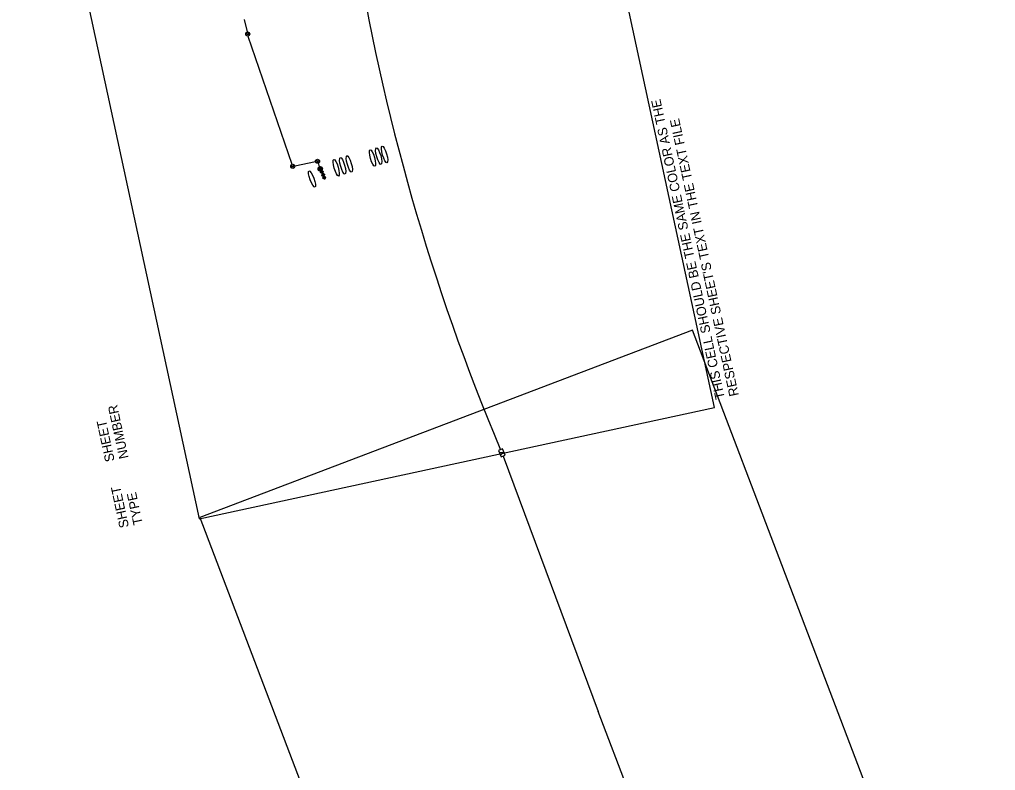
# Model space of a CAD drawing. Extents: x 601462 to 605493, y 331960 to 402715.
# Drawn here: x 601542 to 603347, y 353498 to 354887 of the extents above; entities that cross this region are included whole.
import ezdxf

# ---------------------------------------------------------------- set-up
doc = ezdxf.new("R2010")
doc.units = 0
for name, color, linetype in [('P_FTMS', 7, 'Continuous'), ('P_FTMSConduit', 7, 'Continuous'), ('P_MISC_TXT_2A (Construction)', 7, 'Continuous'), ('P_MISC_TXT_2B (Construction)', 7, 'Continuous')]:
    doc.layers.add(name, color=color, linetype=linetype)

# ---------------------------------------------------------------- blocks, each defined once
blk = doc.blocks.new('FMD')
at = {"layer": 'P_FTMS'}
for p, q in [((17, 18), (-17, 18)), ((-16, 16), (-16, 18)), ((16, 16), (-16, 16)), ((-15, 15), (-15, 20)), ((15, 19), (-15, 19)), ((15, 15), (-15, 15)), ((14, 20), (-14, 20)), ((13, 22), (-13, 22)), ((-13, 13), (-13, 21)), ((13, 13), (-13, 13)), ((-12, 12), (-12, 23)), ((12, 12), (-12, 12)), ((11, 23), (-11, 23)), ((10, 25), (-10, 25)), ((-10, 10), (-10, 24)), ((10, 10), (-10, 10)), ((-9, 9), (-9, 26)), ((9, 9), (-9, 9)), ((8, 26), (-8, 26)), ((7, 28), (-7, 28)), ((-7, 7), (-7, 27)), ((7, 7), (-7, 7)), ((-6, 6), (-6, 29)), ((6, 6), (-6, 6)), ((5, 29), (-5, 29)), ((4, 31), (-4, 31)), ((-4, 4), (-4, 30)), ((4, 4), (-4, 4)), ((-3, 3), (-3, 32)), ((3, 3), (-3, 3)), ((2, 32), (-2, 32)), ((1, 34), (-1, 34)), ((-1, 1), (-1, 33)), ((1, 1), (-1, 1)), ((0, 0), (0, 34)), ((1, 1), (1, 33)), ((3, 3), (3, 32)), ((4, 4), (4, 30)), ((6, 6), (6, 29)), ((7, 7), (7, 27)), ((9, 9), (9, 26)), ((10, 10), (10, 24)), ((12, 12), (12, 23)), ((13, 13), (13, 21)), ((15, 15), (15, 20)), ((16, 16), (16, 18))]:
    blk.add_line(p, q, dxfattribs=at)
blk.add_lwpolyline([(-17, 17), (0, 34), (17, 17), (0, 0)], close=True, dxfattribs=at)
blk = doc.blocks.new('_U233')
at = {"layer": 'P_FTMS'}
for p, q in [((12.1, 1.6), (-12.2, -0.1)), ((11.8, 3), (-12.1, 1.4)), ((11.9, 2.3), (-12.1, 0.6)), ((12.1, 0.8), (-12.1, -0.8)), ((12.1, 0.1), (-12.1, -1.6)), ((11.6, 3.7), (-12, 2.1)), ((-11.9, 2.5), (-11.4, -4.2)), ((11.3, 4.4), (-11.8, 2.9)), ((11, 5.2), (-11.6, 3.6)), ((10.6, 5.9), (-11.4, 4.4)), ((-11.3, 4.5), (-10.6, -6)), ((10.2, 6.6), (-11, 5.1)), ((9.8, 7.3), (-10.7, 5.9)), ((-10.7, 5.9), (-9.8, -7.2)), ((9.2, 8), (-10.2, 6.6)), ((-10, 6.9), (-9, -8.2)), ((8.6, 8.6), (-9.7, 7.4)), ((-9.3, 7.8), (-8.2, -9)), ((7.8, 9.3), (-9, 8.2)), ((-8.6, 8.5), (-7.4, -9.6)), ((6.9, 10), (-8.2, 9)), ((-8, 9.2), (-6.6, -10.2)), ((-7.3, 9.7), (-5.9, -10.6)), ((5.8, 10.7), (-7.2, 9.8)), ((-6.6, 10.3), (-5.1, -11)), ((4.5, 11.3), (-6, 10.6)), ((-5.9, 10.7), (-4.4, -11.4)), ((-5.1, 11), (-3.6, -11.6)), ((-4.4, 11.3), (-2.9, -11.8)), ((2.5, 11.9), (-4.1, 11.5)), ((-3.7, 11.6), (-2.1, -12)), ((-3, 11.8), (-1.4, -12.1)), ((-2.3, 12), (-0.6, -12.2)), ((-1.6, 12.1), (0.1, -12.2)), ((-0.8, 12.1), (0.8, -12.1)), ((-0.1, 12.2), (1.6, -12.1)), ((0.6, 12.1), (2.3, -11.9)), ((1.4, 12.1), (3, -11.8)), ((2.1, 12), (3.7, -11.6)), ((2.9, 11.8), (4.4, -11.3)), ((3.6, 11.6), (5.1, -11)), ((4.4, 11.3), (5.9, -10.7)), ((5.1, 11), (6.6, -10.2)), ((5.9, 10.6), (7.3, -9.8)), ((6.6, 10.2), (8, -9.2)), ((7.4, 9.7), (8.6, -8.6)), ((8.2, 9), (9.3, -7.8)), ((9, 8.2), (10, -6.9)), ((9.8, 7.2), (10.7, -5.8)), ((10.6, 5.9), (11.3, -4.5)), ((11.5, 4), (11.9, -2.5)), ((12.1, -0.6), (-12, -2.3)), ((12.1, -1.4), (-11.8, -3)), ((12, -2.1), (-11.6, -3.7)), ((11.8, -2.9), (-11.3, -4.4)), ((11.6, -3.6), (-11, -5.1)), ((11.3, -4.4), (-10.7, -5.9)), ((11.1, -5.1), (-10.2, -6.6)), ((10.6, -5.9), (-9.8, -7.3)), ((10.2, -6.6), (-9.2, -8)), ((9.6, -7.4), (-8.5, -8.6)), ((9, -8.2), (-7.8, -9.3)), ((8.2, -9), (-6.9, -10)), ((7.3, -9.8), (-5.8, -10.7)), ((6, -10.6), (-4.5, -11.3)), ((4.1, -11.5), (-2.6, -11.9))]:
    blk.add_line(p, q, dxfattribs=at)
blk.add_circle((0, 0), 12.2, dxfattribs=at)
blk = doc.blocks.new('FTMS_FCV')
at = {"layer": 'P_FTMS'}
blk.add_line((13, 16), (1, -22), dxfattribs=at)
blk.add_lwpolyline([(39, 24), (-39, 24), (-39, -24), (39, -24)], close=True, dxfattribs=at)
blk.add_lwpolyline([(-12, 16), (1, -22)], dxfattribs=at)

msp = doc.modelspace()

# ---------------------------------------------------------------- linework, layer by layer
at = {"layer": 'P_FTMS'}
for centre in [(601964.4, 354859.7), (602047.7, 354615.2), (602093.5, 354624.6)]:
    msp.add_circle(centre, 3.75, dxfattribs=at)
for centre, start, end in [((601963.8, 354864.1), 224.5444, 330.8), ((601965, 354855.2), 44.5444, 150.8), ((602047.1, 354619.7), 224.5444, 330.8), ((602048.3, 354610.8), 44.5444, 150.8), ((602092.9, 354629.1), 224.5444, 330.8), ((602094.1, 354620.1), 44.5444, 150.8)]:
    msp.add_arc(centre, 3.75, start, end, dxfattribs=at)
for centre, major_axis in [((602206.7, 354634), (-4.4, 15.4)), ((602217.6, 354637.1), (-4.4, 15.4)), ((602140, 354616.1), (-4.4, 15.4)), ((602152.3, 354619.7), (-4.4, 15.4)), ((602195.2, 354630.6), (-4.4, 15.4)), ((602128.1, 354612.7), (-4.4, 15.4)), ((602083.3, 354591.8), (-5.7, 14.9))]:
    msp.add_ellipse(centre, major_axis=major_axis, ratio=0.23471, dxfattribs=at)
at = {"layer": 'P_FTMSConduit'}
for p, q in [((602046.6, 354618.8), (601965, 354855.2)), ((602051.3, 354616.4), (602089.8, 354623.9)), ((602097.2, 354614.4), (602095.5, 354621.4)), ((602436.7, 354079.4), (602612.7, 353607.2)), ((602781.7, 353163.1), (602612.7, 353607.2))]:
    msp.add_line(p, q, dxfattribs=at)
msp.add_lwpolyline([(601963.8, 354864.1), (601958.2, 354886.6)], dxfattribs=at)
msp.add_arc((606226.2, 355687.6), 4116.5, 189.0802, 202.817, dxfattribs=at)
at = {"layer": 'P_MISC_TXT_2A (Construction)'}
msp.add_lwpolyline([(603347.3, 352840.3), (602787.2, 354312.4), (601876, 353965.7), (602436.1, 352493.6)], close=True, dxfattribs=at)
at = {"layer": 'P_MISC_TXT_2B (Construction)'}
msp.add_lwpolyline([(602827.7, 354169), (602495.5, 355708.6), (601542.4, 355503), (601874.6, 353963.4)], close=True, dxfattribs=at)

# ---------------------------------------------------------------- block references
at = {"layer": 'P_FTMS'}
for name, p, xscale, yscale, rotation in [('_U233', (602098.6, 354610.6), 0.3280833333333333, 0.3280833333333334, -153.80622439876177), ('FMD', (602104.2, 354605.6), 0.16404166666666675, 0.16404166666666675, 112.08663983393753), ('FMD', (602106.4, 354600.4), 0.16404166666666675, 0.16404166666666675, 112.08663983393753), ('FMD', (602108.4, 354595.3), 0.16404166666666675, 0.16404166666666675, 112.08663983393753), ('FTMS_FCV', (602434.3, 354085.4), 0.16404166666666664, 0.1640416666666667, 112.41478162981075)]:
    msp.add_blockref(name, p, dxfattribs=dict(at, xscale=xscale, yscale=yscale, rotation=rotation))

# ---------------------------------------------------------------- texts
at = {"layer": 'P_MISC_TXT_2B (Construction)'}
for s, p in [('THIS CELL SHOULD BE THE SAME COLOR AS THE', (602847, 354186.5)), ("RESPECTIVE SHEET'S TEXT IN THE TEXT FILE", (602872.7, 354192)), ('NUMBER', (601744.2, 354076.4)), ('SHEET', (601718.5, 354070.9)), ('SHEET', (601744.9, 353948.7)), ('TYPE', (601770.6, 353954.2))]:
    msp.add_text(s, height=17.5, rotation=102.1755, dxfattribs=at).set_placement(p)

doc.saveas('drawing.dxf')
